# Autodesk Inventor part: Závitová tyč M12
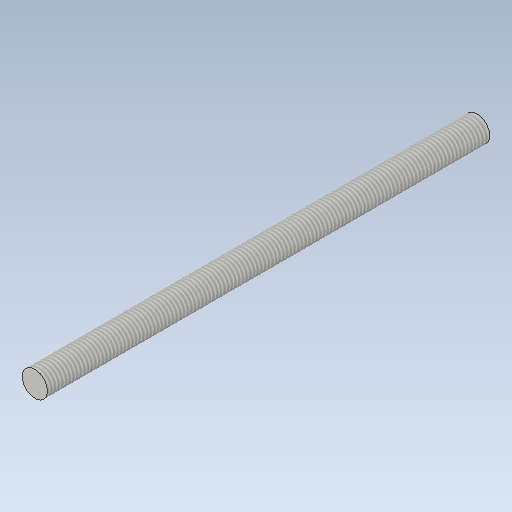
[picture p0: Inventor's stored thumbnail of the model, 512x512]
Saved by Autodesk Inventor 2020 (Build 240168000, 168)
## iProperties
Created: 2025-03
Part Number: Závitová tyč M12
Material: Ocel
Document SubType Name: Modeling
Designer: doma
Density: 7.85 g/cm^3
Appearance: Ocel
Mass: 186.441 g
Surface Area: 81.4301 cm^2
Volume: 23.7504 cm^3
Author: doma
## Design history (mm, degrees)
sketch "Náčrt1"
  geometry: C1 r 6 at (0, 0); 1 further point
  constraints: 1 centre point, 1 coincident
  dimensions: "d0" = 12 diameter of C1
extrude "Vysunutí1" new body sketch "Náčrt1" distance "d1" = 210; taper "d2" = 0 deg
feature "Závit1" dims "d3" = 100, "d4" = 0
node "Těleso1"
